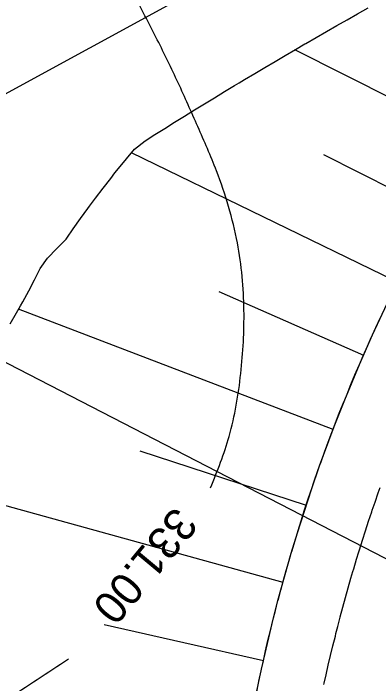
# Model space of a CAD drawing. Extents: x -564043 to -563833, y -1163561 to -1163412.
# Drawn here: x -563869.43 to -563863.75, y -1163500.35 to -1163489.94 of the extents above; entities that cross this region are included whole.
import ezdxf

# ---------------------------------------------------------------- set-up
doc = ezdxf.new("R2010")
doc.units = 0
for name, color, linetype in [('5', 7, 'Continuous'), ('Line', 7, 'Continuous'), ('Vrstva 24', 7, 'Continuous'), ('Vrstva 25', 7, 'Continuous'), ('Vrstva 26', 7, 'Continuous')]:
    doc.layers.add(name, color=color, linetype=linetype)

msp = doc.modelspace()

# ---------------------------------------------------------------- linework, layer by layer
for points in [[(-563865.785, -1163501.206), (-563865.619, -1163500.343), (-563865.574, -1163500.129), (-563865.385, -1163499.33), (-563865.317, -1163499.063), (-563865.111, -1163498.327), (-563865.015, -1163498.009), (-563864.797, -1163497.335), (-563864.669, -1163496.968), (-563864.528, -1163496.58), (-563864.443, -1163496.357), (-563864.28, -1163495.943), (-563864.051, -1163495.394), (-563863.848, -1163494.935), (-563863.62, -1163494.448), (-563863.373, -1163493.946), (-563863.165, -1163493.533), (-563862.713, -1163492.641), (-563862.262, -1163491.749), (-563861.987, -1163491.206), (-563861.81, -1163490.857), (-563861.359, -1163489.964), (-563861.279, -1163489.807)], [(-563869.477, -1163494.761), (-563869.381, -1163494.59), (-563869.32, -1163494.483), (-563869.283, -1163494.421), (-563869.19, -1163494.249), (-563869.102, -1163494.077), (-563869.066, -1163494.008), (-563869.011, -1163493.905), (-563868.898, -1163493.743), (-563868.754, -1163493.595), (-563868.609, -1163493.448), (-563868.599, -1163493.434), (-563868.498, -1163493.287), (-563868.385, -1163493.128), (-563868.27, -1163492.97), (-563868.246, -1163492.937), (-563868.154, -1163492.813), (-563868.036, -1163492.658), (-563867.916, -1163492.504), (-563867.85, -1163492.42), (-563867.795, -1163492.351), (-563867.672, -1163492.2), (-563867.547, -1163492.05), (-563867.383, -1163491.921), (-563867.379, -1163491.919), (-563867.23, -1163491.824), (-563867.077, -1163491.728), (-563866.923, -1163491.632), (-563866.769, -1163491.536), (-563866.615, -1163491.441), (-563866.46, -1163491.346), (-563866.305, -1163491.251), (-563866.149, -1163491.156), (-563865.992, -1163491.062), (-563865.92, -1163491.018), (-563865.836, -1163490.967), (-563865.678, -1163490.873), (-563865.521, -1163490.78), (-563865.362, -1163490.686), (-563865.204, -1163490.593), (-563865.044, -1163490.5), (-563864.898, -1163490.415), (-563864.885, -1163490.407), (-563864.725, -1163490.315), (-563864.564, -1163490.222), (-563864.403, -1163490.13), (-563864.241, -1163490.039), (-563864.079, -1163489.947), (-563863.917, -1163489.856)], [(-563865.645, -1163500.469), (-563865.619, -1163500.343), (-563865.613, -1163500.311), (-563865.579, -1163500.154), (-563865.574, -1163500.129), (-563865.544, -1163499.997), (-563865.508, -1163499.84), (-563865.472, -1163499.683), (-563865.434, -1163499.526), (-563865.395, -1163499.37), (-563865.385, -1163499.33), (-563865.356, -1163499.214), (-563865.317, -1163499.063), (-563865.315, -1163499.058), (-563865.274, -1163498.902), (-563865.231, -1163498.747), (-563865.188, -1163498.592), (-563865.143, -1163498.437), (-563865.111, -1163498.327), (-563865.098, -1163498.283), (-563865.052, -1163498.128), (-563865.015, -1163498.009), (-563865.004, -1163497.974), (-563864.956, -1163497.821), (-563864.907, -1163497.667), (-563864.857, -1163497.514), (-563864.806, -1163497.362), (-563864.797, -1163497.335), (-563864.754, -1163497.209), (-563864.701, -1163497.057), (-563864.669, -1163496.968), (-563864.647, -1163496.905), (-563864.592, -1163496.754), (-563864.536, -1163496.603), (-563864.48, -1163496.452), (-563864.443, -1163496.357), (-563864.422, -1163496.302), (-563864.363, -1163496.152), (-563864.304, -1163496.002), (-563864.28, -1163495.943), (-563864.243, -1163495.853), (-563864.182, -1163495.704), (-563864.12, -1163495.555), (-563864.056, -1163495.407), (-563864.051, -1163495.394), (-563863.992, -1163495.259), (-563863.927, -1163495.112), (-563863.861, -1163494.965), (-563863.848, -1163494.935), (-563863.795, -1163494.819), (-563863.727, -1163494.673)], [(-563864.602, -1163500.367), (-563864.597, -1163500.343), (-563864.568, -1163500.215), (-563864.534, -1163500.064), (-563864.499, -1163499.914), (-563864.462, -1163499.763), (-563864.425, -1163499.613), (-563864.416, -1163499.574), (-563864.387, -1163499.463), (-563864.35, -1163499.318), (-563864.348, -1163499.313), (-563864.308, -1163499.163), (-563864.267, -1163499.014), (-563864.226, -1163498.865), (-563864.183, -1163498.716), (-563864.152, -1163498.61), (-563864.139, -1163498.567), (-563864.095, -1163498.419), (-563864.06, -1163498.304), (-563864.049, -1163498.271), (-563864.003, -1163498.123), (-563863.956, -1163497.976), (-563863.908, -1163497.829), (-563863.858, -1163497.682), (-563863.85, -1163497.656), (-563863.808, -1163497.535), (-563863.757, -1163497.389), (-563863.727, -1163497.303)]]:
    msp.add_lwpolyline(points)
at = {"layer": '5'}
for p, q in [((-563897.15, -1163506.247), (-563862.812, -1163487.513)), ((-563871.424, -1163494.398), (-563841.172, -1163509.993))]:
    msp.add_line(p, q, dxfattribs=at)
at = {"layer": 'Line'}
for p, q in [((-563862.33, -1163491.884), (-563865.054, -1163490.506)), ((-563863.457, -1163494.115), (-563867.593, -1163492.106)), ((-563864.611, -1163492.132), (-563862.894, -1163492.999)), ((-563866.237, -1163494.262), (-563863.986, -1163495.248)), ((-563864.459, -1163496.404), (-563869.35, -1163494.536)), ((-563867.464, -1163496.734), (-563864.877, -1163497.582)), ((-563865.238, -1163498.779), (-563870.41, -1163497.354)), ((-563868.019, -1163499.435), (-563865.541, -1163499.991))]:
    msp.add_line(p, q, dxfattribs=at)
at = {"layer": 'Vrstva 24'}
for points in [[(-563866.364, -1163497.311), (-563866.075, -1163496.511), (-563865.895, -1163495.533), (-563865.845, -1163494.553), (-563865.947, -1163493.507), (-563866.272, -1163492.388), (-563866.563, -1163491.699), (-563866.868, -1163491.02), (-563867.192, -1163490.352), (-563867.536, -1163489.691), (-563869.125, -1163486.92), (-563869.85, -1163485.772), (-563870.624, -1163484.653), (-563871.666, -1163483.346), (-563872.824, -1163482.142), (-563874.562, -1163480.618), (-563875.472, -1163479.893), (-563878.363, -1163477.556), (-563882.755, -1163474.046), (-563884.234, -1163472.969), (-563885.61, -1163472.026), (-563886.998, -1163471.1), (-563889.83, -1163469.34), (-563892.347, -1163467.891)], [(-563852.947, -1163500.287), (-563852.983, -1163499.934), (-563853.278, -1163497.907), (-563853.324, -1163497.501), (-563853.384, -1163496.604), (-563853.408, -1163496.155), (-563853.449, -1163495.707), (-563853.76, -1163494.797), (-563854.364, -1163493.737), (-563856.816, -1163489.636), (-563859.313, -1163485.439), (-563859.915, -1163484.694), (-563860.397, -1163484.207), (-563862.509, -1163482.09), (-563867.011, -1163477.664), (-563868.116, -1163476.702), (-563871.116, -1163474.41), (-563872.986, -1163473.06), (-563873.689, -1163472.566), (-563878.103, -1163469.411), (-563878.316, -1163469.26)], [(-563905.221, -1163519.388), (-563901.417, -1163517.444), (-563900.291, -1163516.907), (-563895.909, -1163514.815), (-563892.135, -1163512.984), (-563890.63, -1163512.267), (-563888.864, -1163511.357), (-563887.99, -1163510.869), (-563887.125, -1163510.367), (-563886.26, -1163509.866), (-563885.383, -1163509.384), (-563882.362, -1163507.826), (-563880.585, -1163506.938), (-563878.549, -1163505.818), (-563872.848, -1163502.599), (-563870.632, -1163501.288), (-563869.542, -1163500.601), (-563868.575, -1163499.969)]]:
    msp.add_spline(points, degree=3, dxfattribs=at)
at = {"layer": 'Vrstva 26'}
for points in [[(-563838.029, -1163497.163), (-563838.58, -1163496.19), (-563840.28, -1163493.165), (-563841.199, -1163491.578), (-563841.674, -1163490.793), (-563842.159, -1163490.013), (-563843.649, -1163487.993), (-563844.702, -1163486.757), (-563850.461, -1163480.038), (-563851.089, -1163479.371), (-563851.956, -1163478.574), (-563857.613, -1163473.501), (-563859.731, -1163471.636), (-563864.022, -1163468.083), (-563864.562, -1163467.631), (-563865.045, -1163467.216), (-563865.679, -1163466.68)], [(-563859.41, -1163497.306), (-563859.213, -1163496.32), (-563859.173, -1163495.343), (-563859.23, -1163495.062), (-563859.315, -1163494.786), (-563859.559, -1163494.264), (-563860.664, -1163492.33), (-563861.767, -1163490.395), (-563863.612, -1163487.077), (-563864.619, -1163485.435), (-563865.167, -1163484.642), (-563865.744, -1163483.864), (-563868.01, -1163481.46), (-563871.348, -1163478.665), (-563874.529, -1163476.131), (-563879.25, -1163472.365), (-563881.038, -1163471.025), (-563881.839, -1163470.479), (-563883.542, -1163469.415), (-563886.341, -1163467.718)], [(-563846.143, -1163505.119), (-563846.16, -1163504.298), (-563846.784, -1163499.435), (-563846.859, -1163499.141), (-563847.15, -1163498.47), (-563847.685, -1163497.291), (-563847.809, -1163497.032), (-563850.257, -1163492.396), (-563853.06, -1163487.093), (-563853.131, -1163486.997), (-563856.933, -1163483.04), (-563859.434, -1163480.56), (-563863.484, -1163476.533), (-563865.168, -1163474.917), (-563866.123, -1163474.143), (-563868.988, -1163472.112)]]:
    msp.add_spline(points, degree=3, dxfattribs=at)

# ---------------------------------------------------------------- texts
at = {"layer": 'Vrstva 25'}
msp.add_text('331.00', height=0.5, rotation=230.2626, dxfattribs=at).set_placement((-563866.917, -1163497.579))

doc.saveas('drawing.dxf')
